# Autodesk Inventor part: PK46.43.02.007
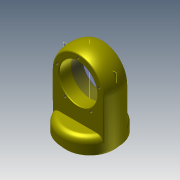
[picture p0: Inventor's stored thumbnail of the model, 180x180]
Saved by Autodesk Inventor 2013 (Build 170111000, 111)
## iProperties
Shininess: 20.0
Length Units: 11269
Angle Units: 11279
Time Units: 11290
Mass Units: 11283
Length Display Precision: 3
Angle Display Precision: 2
Created: 2001-08
Part Number: PK46.43.02.007
Material: Steel, Mild
Document SubType Name: Modeling
Designer: SOleg
Density: 7.86 g/cm^3
Mass: 21280.5 g
Surface Area: 1948.13 cm^2
Volume: 2707.44 cm^3
Density: 0.0
Volumn: 0.0
Area: 0.0
PropertySet Name: Model Information
Control State: 0
Master: False
Checked Out: True
Checked Out Date: 2008-10-09
Last Check In Date: 2008-10-09
Title: Крышка
Author: SOleg
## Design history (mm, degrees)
node "WorkPlane4"
node "WorkPlane3"
node "WorkPlane5"
node "WorkPlane6"
sketch "Sketch1"
  geometry: L1 (0, -102.5)-(0, 160); L2 (92.5, 67.5)-(92.5, -86.5); L3 (92.5, -86.5)-(82.5, -86.5); L4 (82.5, -86.5)-(82.5, -88.5); L5 (82.5, -88.5)-(80, -88.5); L6 (80, -88.5)-(80, -100.5); L7 (80, -100.5)-(78, -102.5); L8 (78, -102.5)-(0, -102.5); L9 (0, -102.5)-(0, 160); A1 r 92.5 centre (0, 67.5) between (92.5, 67.5) and (0, 160)
  constraints: 18 end point, 4 vertical, 3 horizontal, 2 point on circle, 1 centre point, 1 tangent, 1 other
  dimensions: "d4" = 170 distance of A1.centre L1.start; "d6" = 0 horizontal distance of A1.centre L1.end; "d8" = 2 horizontal distance of L6.end L7.end; "d10" = 2 horizontal distance of L6.end L7.end; "d12" = 14 vertical distance of L5.end L7.end; "d14" = 16 vertical distance of L2.end L7.end; "d16" = 80 horizontal distance of L5.end L1.start; "d18" = 82.5 horizontal distance of L4.end L1.start; "d20" = 92.5 horizontal distance of L2.end L1.start
revolve "RevolutionAngle1" sketch "Sketch1" stored, may be unused: angle "d21" = 360 deg
sketch "Sketch2"
  geometry: L1 through (81.534, 0) direction (1, 0)
  constraints: 2 horizontal, 1 end point
node "WorkAxis2"
node "WorkAxis3"
sketch "Sketch3"
  geometry: L1 (92.5, -56.5)-(92.5, -35.5); L2 (92.5, -35.5)-(87.5, -35.5); L3 (87.5, -35.5)-(87.5, -46.5); L4 (87.5, -46.5)-(40, -46.5); L5 (40, -46.5)-(40, -56.5); L6 (40, -56.5)-(92.5, -56.5); L7 (170.115, -56.5)-(-170.115, -56.5); C1 r 78 at (0, -102.5)
  constraints: 14 end point, 3 horizontal, 3 vertical, 1 centre point
  dimensions: "d24" = 5 distance of L1.end L2.end; "d26" = 52.5 distance of L5.end L1.start; "d28" = 10 distance of L4.end L5.end; "d30" = 21 distance of L1.start L1.end; "d32" = 46 vertical distance of L1.start C1.centre
revolve "RevolutionAngle4" sketch "Sketch3" stored, may be unused: angle "d33" = 360 deg
sketch "Sketch4"
  geometry: L1 (-92.5, -42.5)-(-92.5, 207.5); L2 (-40, -42.5)-(-92.5, -42.5); L3 (-40, 207.5)-(-40, -42.5); L4 (-92.5, 207.5)-(-40, 207.5); L5 (40, -42.5)-(40, 207.5); L6 (92.5, -42.5)-(40, -42.5); L7 (92.5, 207.5)-(92.5, -42.5); L8 (40, 207.5)-(92.5, 207.5); L9 (78, -102.5)-(-78, -102.5) reference; C1 r 78 at (0, -102.5)
  constraints: 16 end point, 4 horizontal, 4 vertical, 2 collinear, 1 centre point, 1 midpoint
  dimensions: "d35" = 80 distance of L3.start L5.end; "d37" = 52.5 distance of L5.end L7.start; "d39" = 52.5 distance of L1.end L3.start; "d41" = 250 distance of L7.start L6.start; "d43" = 60 vertical distance of L6.start C1.centre
extrude "ExtrusionMidplane1" cut sketch "Sketch4" stored distance "d44" = 185; taper "d45" = 0 deg
fillet "Fillet1" dims "d46" = 20
fillet "Fillet2" dims "d47" = 5
sketch "Sketch5"
  geometry: L1 (0, -102.5)-(0, -68.5); L2 (55, -102.5)-(0, -102.5); L3 (55, -68.5)-(55, -102.5); L4 (0, -68.5)-(55, -68.5); L5 (0, -163.865)-(0, 176.365); C1 r 78 at (0, -102.5)
  constraints: 10 end point, 2 horizontal, 2 vertical, 1 centre point, 1 coincident
  dimensions: "d49" = 34 distance of L3.start L2.start; "d51" = 55 distance of L2.start L1.start; "d53" = 0 vertical distance of L2.start C1.centre (derived)
revolve "RevolutionAngle5" sketch "Sketch5" stored, may be unused: angle "d54" = 360 deg
node "WorkAxis4"
fillet "Fillet3" dims "d55" = 3
sketch "Sketch6"
  geometry: L1 (27.5, -43.5)-(37.5, -37.726); L2 (27.5, -99.5)-(27.5, -43.5); L3 (37.5, -99.5)-(27.5, -99.5); L4 (37.5, -37.726)-(37.5, -99.5); L5 (37.5, -37.726)-(37.5, -99.5); C1 r 55 at (-0.5, -99.5)
  constraints: 10 end point, 2 vertical, 1 centre point, 1 horizontal
  dimensions: "d57" = 10 distance of L3.start L2.start; "d59" = 56 distance of L2.start L1.start; "d61" = 60 deg angle of L1 L4; "d63" = 0 vertical distance of L2.start C1.centre; "d120" = 38 distance from line of C1.centre L4
revolve "RevolutionAngle6" sketch "Sketch6" stored, may be unused: angle "d64" = 360 deg
sketch "Sketch7"
  geometry: L1 (0, 22.5)-(162.124, 22.5)
  constraints: 2 end point
node "WorkAxis5"
sketch "Sketch9"
  geometry: L1 (-19.728, -110)-(-19.728, 9.656) reference; L2 (60.467, -110)-(60.467, -155); L3 (-8.485, -132.404)-(60.467, -110); L4 (60.467, -110)-(17.853, -51.346); L5 (60.467, -110)-(103.081, -51.346); L6 (60.467, -110)-(129.419, -132.404); L7 (-17.533, 60)-(138.467, 60) reference; L8 (-19.533, 58)-(-19.533, 46) reference; C1 r 5 at (60.467, -182.5); C2 r 5 at (-8.485, -132.404); C3 r 5 at (17.853, -51.346); C4 r 5 at (103.081, -51.346); C5 r 5 at (129.419, -132.404); A1 r 80.195 centre (60.467, -110) between (-19.728, -110) and (140.662, -110) reference; A2 r 72.5 centre (60.467, -110) between (-8.485, -132.404) and (17.853, -51.346)
  constraints: 10 end point, 6 centre point, 4 equal radius, 4 point on circle, 1 coincident, 1 parallel
  dimensions: "d80" = 10 diameter of C1; "d83" = 72 deg angle of L3 L2; "d84" = 72 deg angle of L2 L6; "d85" = 144 deg angle of L4 L2; "d86" = 144 deg angle of L5 L2; "d87" = 145 diameter of A2; "d131" = 72.5 distance of C1.centre L2.start
hole "Hole1" sketch "Sketch9" at (17.853, -51.346), (103.081, -51.346), (129.419, -132.404), (60.467, -182.5), (-8.485, -132.404) diameter "d88" = 10; stored, may be unused: countersink angle "d92" = 82 deg, drill point angle "d94" = 118 deg; dims "d89" = 6, "d90" = 4, "d91" = 2, "d93" = 16
chamfer "Chamfer1" distance "d95" = 1; stored, may be unused: second distance "d96" = 1, angle "d132" = 45 deg
sketch "Эскиз10"
  geometry: L1 (-17.533, 60)-(138.467, 60) reference; L2 (140.467, 58)-(140.467, 46) reference; A1 r 80.195 centre (60.467, -110) between (-19.728, -110) and (140.662, -110) reference; 1 further point
  constraints: 1 coincident
hole "Отверстие2" sketch "Эскиз10" diameter "d101" = 125; stored, may be unused: countersink angle "d105" = 82 deg, drill point angle "d107" = 118 deg; dims "d102" = 6, "d103" = 129, "d104" = 2, "d106" = 40
node "РабПлоскость5"
node "РабОсь5"
mirror "ЗеркОтобр1"
feature "Резьба1" dims "d109" = 10, "d110" = 0
feature "Резьба2" dims "d111" = 10, "d112" = 0
feature "Резьба3" dims "d113" = 10, "d114" = 0
feature "Резьба4" dims "d115" = 10, "d116" = 0
feature "Резьба5" dims "d117" = 10, "d118" = 0
mirror "ЗеркОтобр2"
feature "Резьба6" dims "d121" = 10, "d122" = 0
feature "Резьба7" dims "d123" = 10, "d124" = 0
feature "Резьба8" dims "d125" = 10, "d126" = 0
feature "Резьба9" dims "d127" = 10, "d128" = 0
feature "Резьба10" dims "d129" = 10, "d130" = 0
body "Solid1"
other parameters: "d0" = -92.5, "d1" = -46, "d2" = -125, "d3" = 125 (derived), "d5" = 0 (derived), "d7" = 2 (derived), "d9" = 2 (derived), "d11" = 13 (derived), "d13" = 16 (derived), "d17" = 82.5 (derived), "d19" = 92.5 (derived), "d22" = 0, "d23" = 5 (derived), "d25" = 52.5 (derived), "d27" = 12.5 (derived), "d29" = 21.5 (derived), "d31" = 46 (derived), "d36" = 52.5 (derived), "d38" = 52.5 (derived), "d42" = 55 (derived), "d48" = 34 (derived), "d50" = 55 (derived), "d52" = 0 (derived), "d56" = 12.5 (derived), "d58" = 59 (derived), "d60" = 60 deg (derived), "d62" = 0 (derived), "d65" = 5 (derived), "d67" = 5 (derived), "d69" = 2 (derived), "d71" = 2 (derived), "d73" = 57.5 (derived), "d77" = 0 (derived)
